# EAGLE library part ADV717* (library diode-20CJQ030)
Analog's ADV7170 / ADV7171 Digital PAL/NTSC Video Encoder with 10-Bit SSAF and Advanced Power Management Description: The ADV7170/ADV7171 are integrated digital video encoders that convert digital CCIR-601 4:2:2 8- or 16-bit component video data into a standard analog baseband television signal compatible with worldwide standards. The on-board SSAF (super sub-alias filter) with extended luminance frequency response and sharp stop band attenuation enables studio-quality video playback on modern TVs, giving optimal horizontal line resolution. An advanced power management circuit enables optimal control of power consumption in both normal operating modes and power-down or sleep modes. The ADV7170/ADV7171 support both PAL and NTSC square pixel operation. The parts also incorporate WSS and CGMS-A data control generation. The output video frames are synchronized with the incoming data timing reference codes. Optionally, the encoder accepts and can generate HSYNC, VSYNC, and FIELD timing signals. These timing signals can be adjusted to change pulse width and position while the part is in the master mode. The encoder requires a single, two-times pixel rate (27 MHz) clock for standard operation. Alternatively, the encoder requires a 24.5454 MHz clock for NTSC or 29.5 MHz clock for PAL square pixel mode operation. All internal timing is generated on-chip. A separate teletext port enables the user to directly input teletext data during the vertical blanking interval. The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
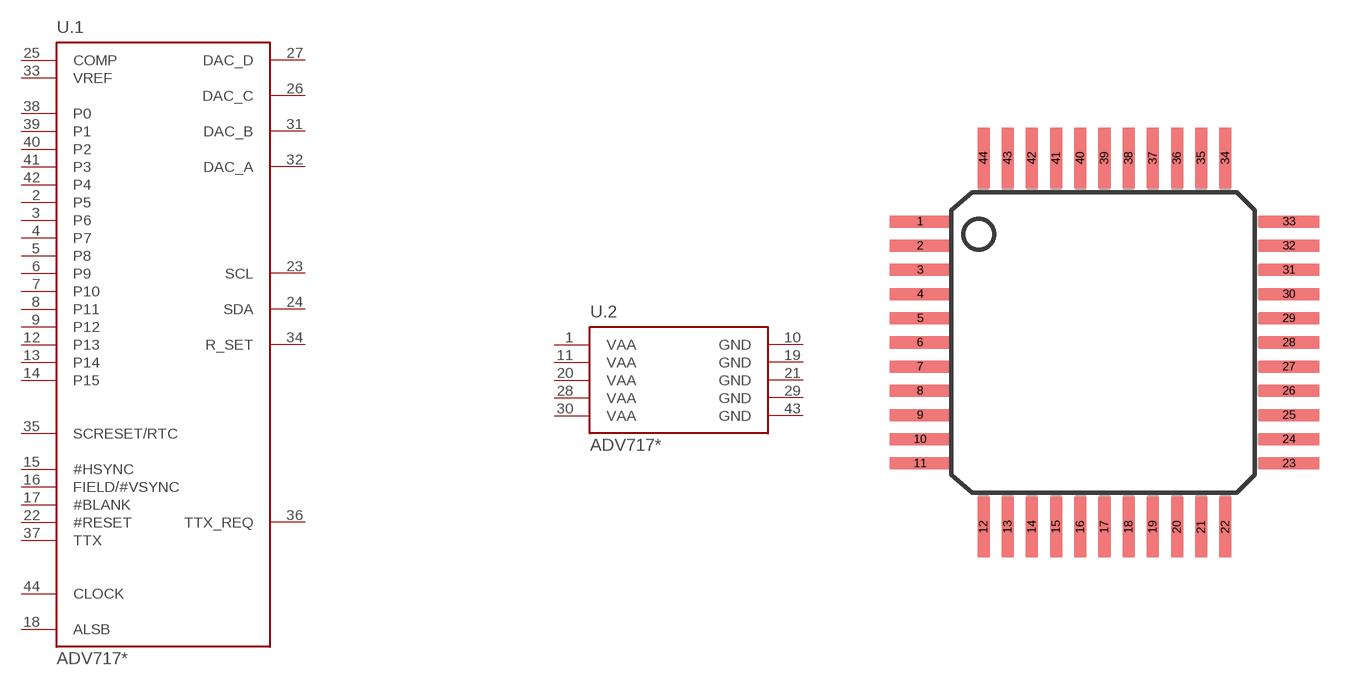
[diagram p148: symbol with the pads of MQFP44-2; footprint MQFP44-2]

Designator prefix U; gates .1=ADV7175_76 .2=ADV7175A_76A_PWR

## ADV717S-44-1  [MQFP44-2]
1  .2:VAA  pwr
2  .1:P5  in
3  .1:P6  in
4  .1:P7  in
5  .1:P8  in
6  .1:P9  in
7  .1:P10  in
8  .1:P11  in
9  .1:P12  in
10  .2:GND  pwr
11  .2:VAA  pwr
12  .1:P13  in
13  .1:P14  in
14  .1:P15  in
15  .1:#HSYNC
16  .1:FIELD/#VSYNC
17  .1:#BLANK
18  .1:ALSB  in
19  .2:GND  pwr
20  .2:VAA  pwr
21  .2:GND  pwr
22  .1:#RESET  in
23  .1:SCL  in
24  .1:SDA
25  .1:COMP  in
26  .1:DAC_C  out
27  .1:DAC_D  out
28  .2:VAA  pwr
29  .2:GND  pwr
30  .2:VAA  pwr
31  .1:DAC_B  out
32  .1:DAC_A  out
33  .1:VREF
34  .1:R_SET  in
35  .1:SCRESET/RTC  in
36  .1:TTX_REQ  out
37  .1:TTX  in
38  .1:P0  in
39  .1:P1  in
40  .1:P2  in
41  .1:P3  in
42  .1:P4  in
43  .2:GND  pwr
44  .1:CLOCK  in

## Footprint MQFP44-2 (pad centres in mm)
Metric Quad Flat Pack
smd 2 x 0.4: 1 -6.1,4; 2 -6.1,3.2; 3 -6.1,2.4; 4 -6.1,1.6; 5 -6.1,0.8; 6 -6.1,0; 7 -6.1,-0.8; 8 -6.1,-1.6; 9 -6.1,-2.4; 10 -6.1,-3.2; 11 -6.1,-4; 23 6.1,-4; 24 6.1,-3.2; 25 6.1,-2.4; 26 6.1,-1.6; 27 6.1,-0.8; 28 6.1,0; 29 6.1,0.8; 30 6.1,1.6; 31 6.1,2.4; 32 6.1,3.2; 33 6.1,4
smd 0.4 x 2: 12 -4,-6.1; 13 -3.2,-6.1; 14 -2.4,-6.1; 15 -1.6,-6.1; 16 -0.8,-6.1; 17 0,-6.1; 18 0.8,-6.1; 19 1.6,-6.1; 20 2.4,-6.1; 21 3.2,-6.1; 22 4,-6.1; 34 4,6.1; 35 3.2,6.1; 36 2.4,6.1; 37 1.6,6.1; 38 0.8,6.1; 39 0,6.1; 40 -0.8,6.1; 41 -1.6,6.1; 42 -2.4,6.1; 43 -3.2,6.1; 44 -4,6.1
